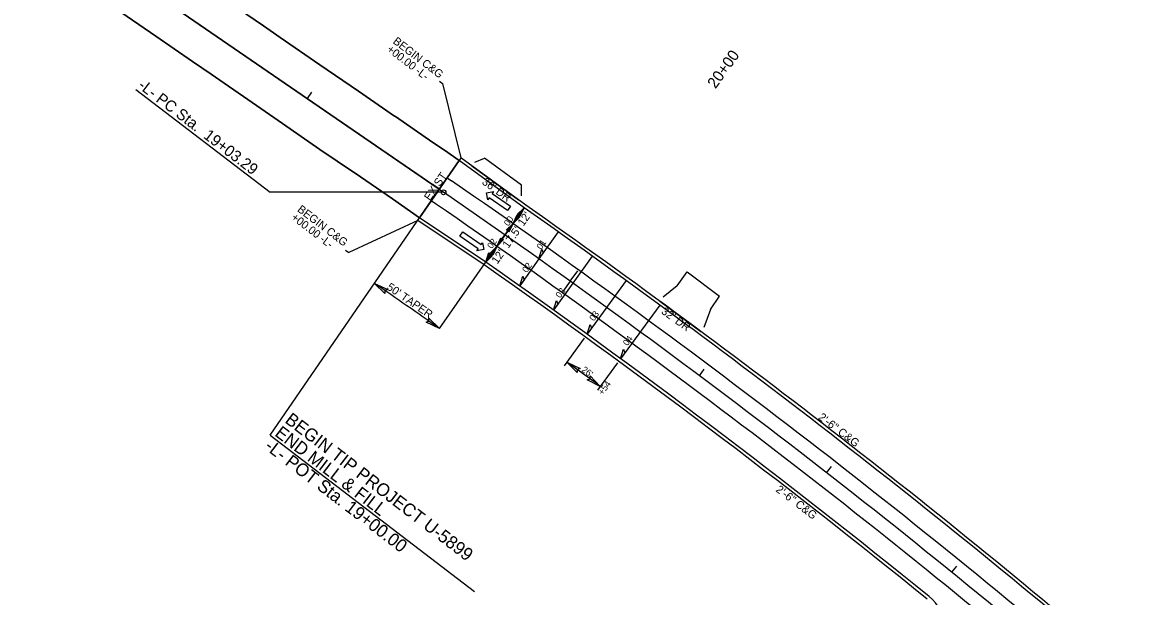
# Model space of a CAD drawing. Extents: x 1616561 to 1622460, y 896726 to 899651.
# Drawn here: x 1618541 to 1619243, y 898351 to 898710 of the extents above; entities that cross this region are included whole.
import ezdxf

# ---------------------------------------------------------------- set-up
doc = ezdxf.new("R2010")
doc.units = 0
for name, color, linetype in [('Old_Level_3', 7, 'Continuous'), ('Prop Conc Drive Radius Type', 7, 'Continuous'), ('Prop Dimension', 7, 'Continuous'), ('Prop DSN Text', 7, 'Continuous'), ('Prop Horizontal Alignment Tick Small', 7, 'Continuous'), ('Prop Lane Arrow CELL', 7, 'Continuous'), ('Prop North Arrow NAD83 for Plan Sheets CELL', 7, 'Continuous'), ('Prop Shade Light', 7, 'Continuous'), ('Prop Superelevation  Arrow CELL', 7, 'Continuous'), ('Prop Superelevation Label', 7, 'Continuous'), ('Prop Terminator CELL', 7, 'Continuous'), ('Scratch_Level_1', 7, 'Continuous'), ('Sheet Cutting Line CELL', 7, 'Continuous'), ('Sheet North Arrow CELL', 7, 'Continuous'), ('Sheet Sticker Preliminary CELL', 7, 'Continuous')]:
    doc.layers.add(name, color=color, linetype=linetype)

msp = doc.modelspace()

# ---------------------------------------------------------------- linework, layer by layer
at = {"layer": 'Old_Level_3'}
for p, q in [((1618796.38, 898598.52), (1618806.28, 898612.95)), ((1618806.28, 898612.95), (1618809, 898611.08)), ((1618799.08, 898596.66), (1618796.38, 898598.52))]:
    msp.add_line(p, q, dxfattribs=at)
for radius, start in [(5008.75, 49.34838), (4991.25, 49.50113)]:
    msp.add_arc((1615970.53, 894484.25), radius, start, 55.47944, dxfattribs=at)
at = {"layer": 'Prop Conc Drive Radius Type'}
for p, q in [((1618821.78, 898620.36), (1618850.89, 898599.2)), ((1618939.16, 898535.82), (1618964.88, 898516.84))]:
    msp.add_line(p, q, dxfattribs=at)
at = {"layer": 'Prop Dimension'}
for p, q in [((1618854.32, 898594.21), (1618847.43, 898584.38)), ((1618847.43, 898584.38), (1618837.37, 898570.06)), ((1618801.41, 898518.8), (1618842.4, 898577.22)), ((1618837.37, 898570.06), (1618830.48, 898560.23))]:
    msp.add_line(p, q, dxfattribs=at)
msp.add_arc((1615970.53, 894484.25), 4928.63, 54.94423, 55.51773, dxfattribs=at)
at = {"layer": 'Prop DSN Text'}
for p, q in [((1618801.42, 898673.34), (1618803.39, 898671.82)), ((1618803.39, 898671.82), (1618814.85, 898625.39)), ((1618787.93, 898586.26), (1618744.83, 898566.28)), ((1618742.85, 898567.79), (1618744.83, 898566.28))]:
    msp.add_line(p, q, dxfattribs=at)
at = {"layer": 'Prop Horizontal Alignment Tick Small'}
for p, q in [((1618814.85, 898625.39), (1618813.71, 898623.74)), ((1618855.5, 898595.82), (1618814.85, 898625.39)), ((1618787.93, 898586.26), (1618789.06, 898587.9)), ((1618829.37, 898558.57), (1618787.93, 898586.26))]:
    msp.add_line(p, q, dxfattribs=at)
for radius, start in [(5022.75, 49.34838), (4977.25, 50.95117)]:
    msp.add_arc((1615970.53, 894484.25), radius, start, 54.94423, dxfattribs=at)
at = {"layer": 'Prop Lane Arrow CELL'}
for p, q in [((1618830.84, 898603.55), (1618835.25, 898604.37)), ((1618831.65, 898599.2), (1618830.84, 898603.55)), ((1618832.51, 898600.43), (1618831.65, 898599.2)), ((1618843.99, 898592.43), (1618832.51, 898600.43)), ((1618835.25, 898604.37), (1618834.39, 898603.14)), ((1618834.39, 898603.14), (1618845.88, 898595.13)), ((1618845.88, 898595.13), (1618843.99, 898592.43)), ((1618814.13, 898576.45), (1618816.02, 898579.16)), ((1618825.61, 898568.45), (1618814.13, 898576.45)), ((1618816.02, 898579.16), (1618827.5, 898571.15)), ((1618827.5, 898571.15), (1618828.36, 898572.38)), ((1618828.36, 898572.38), (1618829.17, 898568.04)), ((1618824.76, 898567.22), (1618825.61, 898568.45)), ((1618829.17, 898568.04), (1618824.76, 898567.22))]:
    msp.add_line(p, q, dxfattribs=at)
at = {"layer": 'Prop North Arrow NAD83 for Plan Sheets CELL'}
for points in [[(1618830.48, 898560.23), (1618832.29, 898566.29), (1618833.14, 898564.02)], [(1618863.64, 898562.23), (1618865.49, 898568.28), (1618866.32, 898566)], [(1618851.64, 898545.31), (1618853.48, 898551.36), (1618854.31, 898549.08)], [(1618872.72, 898530.27), (1618874.59, 898536.31), (1618875.41, 898534.03)], [(1618893.72, 898515.12), (1618895.62, 898521.16), (1618896.43, 898518.87)], [(1618914.64, 898499.87), (1618916.57, 898505.89), (1618917.37, 898503.6)]]:
    msp.add_lwpolyline(points, close=True, dxfattribs=at)
at = {"layer": 'Prop Shade Light'}
for p, q in [((1618059.8, 899115.77), (1618801.33, 898605.73)), ((1618801.33, 898605.73), (1618059.8, 899115.77)), ((1618789.06, 898587.9), (1618801.33, 898605.73))]:
    msp.add_line(p, q, dxfattribs=at)
for points in [[(1618773.4, 898651.52), (1618750.87, 898667.1), (1618726.65, 898683.63), (1618702.01, 898700.61), (1618691.56, 898707.86), (1618670.18, 898722.47), (1618646.62, 898738.71), (1618621.31, 898755.98), (1618596.1, 898773.27), (1618578.76, 898785.19), (1618566.83, 898793.5), (1618556.18, 898800.72), (1618539.02, 898812.52)], [(1618532.75, 898764.19), (1618555.15, 898748.82), (1618573.55, 898736.29), (1618599.06, 898718.7), (1618624.26, 898701.44), (1618647.12, 898685.72), (1618658.86, 898677.65), (1618669.7, 898670.24), (1618679.04, 898663.8), (1618703.51, 898646.86), (1618726.83, 898630.68), (1618748.38, 898616.08), (1618748.82, 898615.73)], [(1618813.7, 898623.72), (1618804.53, 898630.14), (1618797.41, 898634.99), (1618773.92, 898651.22), (1618773.4, 898651.52)], [(1618801.33, 898605.73), (1618806.29, 898612.94), (1618813.7, 898623.72)], [(1618748.82, 898615.73), (1618772.07, 898599.73), (1618789.06, 898587.9)]]:
    msp.add_lwpolyline(points, dxfattribs=at)
at = {"layer": 'Prop Superelevation  Arrow CELL'}
for p, q in [((1618718.94, 898662.4), (1618721.77, 898666.52)), ((1618801.33, 898605.73), (1618804.16, 898609.85)), ((1618963.88, 898489.23), (1618966.87, 898493.24)), ((1619043.37, 898428.57), (1619046.45, 898432.52)), ((1619121.64, 898366.33), (1619124.79, 898370.21))]:
    msp.add_line(p, q, dxfattribs=at)
at = {"layer": 'Prop Superelevation Label'}
for q in [(1618887.85, 898554.8), (1618878.53, 898541.79)]:
    msp.add_line((1618883.19, 898548.3), q, dxfattribs=at)
at = {"layer": 'Prop Terminator CELL'}
for p, q in [((1618773.4, 898651.52), (1618773.92, 898651.22)), ((1618789.06, 898587.9), (1618813.71, 898623.74)), ((1618813.71, 898623.74), (1618789.06, 898587.9)), ((1618854.32, 898594.21), (1618813.71, 898623.74)), ((1618823.55, 898622.79), (1618829.68, 898625.17)), ((1618852.73, 898608.41), (1618829.68, 898625.17)), ((1618748.82, 898615.73), (1618748.38, 898616.08)), ((1618852.66, 898601.62), (1618852.73, 898608.41)), ((1618830.48, 898560.23), (1618789.06, 898587.9)), ((1618950.1, 898545.46), (1618956.21, 898554.21)), ((1618956.21, 898554.21), (1618976.37, 898538.91)), ((1618950.1, 898545.46), (1618941.17, 898538.38)), ((1618970.8, 898530.66), (1618976.37, 898538.91)), ((1618970.8, 898530.66), (1618966.66, 898519.26))]:
    msp.add_line(p, q, dxfattribs=at)
for points in [[(1618539.02, 898812.52), (1618556.18, 898800.72), (1618566.83, 898793.5), (1618578.76, 898785.19), (1618596.1, 898773.27), (1618621.31, 898755.98), (1618646.62, 898738.71), (1618670.18, 898722.47), (1618691.56, 898707.86), (1618702.01, 898700.61), (1618726.65, 898683.63), (1618750.87, 898667.1), (1618773.4, 898651.52)], [(1618748.38, 898616.08), (1618726.83, 898630.68), (1618703.51, 898646.86), (1618679.04, 898663.8), (1618669.7, 898670.24), (1618658.86, 898677.65), (1618647.12, 898685.72), (1618624.26, 898701.44), (1618599.06, 898718.7), (1618573.55, 898736.29), (1618555.15, 898748.82), (1618532.75, 898764.19)], [(1618773.92, 898651.22), (1618797.41, 898634.99), (1618804.53, 898630.14), (1618813.7, 898623.72)], [(1618789.06, 898587.9), (1618772.07, 898599.73), (1618748.82, 898615.73)]]:
    msp.add_lwpolyline(points, dxfattribs=at)
for points in [[(1618850.13, 898590), (1618854.32, 898594.21), (1618851.79, 898588.79), (1618851.37, 898590)], [(1618843.24, 898580.17), (1618847.43, 898584.38), (1618844.9, 898578.97), (1618844.48, 898580.18)], [(1618851.61, 898588.59), (1618847.43, 898584.38), (1618849.95, 898589.8), (1618850.38, 898588.59)], [(1618833.19, 898565.85), (1618837.37, 898570.06), (1618834.85, 898564.64), (1618834.43, 898565.85)], [(1618841.56, 898574.27), (1618837.37, 898570.06), (1618839.9, 898575.47), (1618840.32, 898574.26)], [(1618834.67, 898564.44), (1618830.48, 898560.23), (1618833.01, 898565.65), (1618833.43, 898564.44)], [(1618767.43, 898540.56), (1618760.88, 898546.93), (1618769.25, 898543.13), (1618767.4, 898542.46)], [(1618794.93, 898525.24), (1618801.41, 898518.8), (1618793.08, 898522.69), (1618794.94, 898523.34)], [(1618887.51, 898491.23), (1618881.13, 898497.77), (1618889.4, 898493.75), (1618887.53, 898493.13)], [(1618895.62, 898489.15), (1618901.96, 898482.58), (1618893.72, 898486.64), (1618895.59, 898487.25)]]:
    msp.add_lwpolyline(points, close=True, dxfattribs=at)
for centre, radius, start, end in [((1615970.53, 894484.25), 5020.75, 49.34838, 54.94423), ((1615970.53, 894484.25), 4979.25, 50.95117, 54.94423), ((1619090.36, 898330.22), 27, 315.29135, 50.95117)]:
    msp.add_arc(centre, radius, start, end, dxfattribs=at)
at = {"layer": 'Scratch_Level_1'}
msp.add_line((1618695.66, 898452.1), (1618823.31, 898354.34), dxfattribs=at)
at = {"layer": 'Sheet Cutting Line CELL'}
msp.add_line((1618059.8, 899115.77), (1618804.04, 898603.87), dxfattribs=at)
msp.add_arc((1615970.53, 894484.25), 5000, 49.34838, 55.47944, dxfattribs=at)
at = {"layer": 'Sheet North Arrow CELL'}
for p, q in [((1618611.83, 898668.16), (1618695.75, 898603.89)), ((1618695.66, 898452.1), (1618801.33, 898605.73)), ((1618804.04, 898603.87), (1618695.75, 898603.89))]:
    msp.add_line(p, q, dxfattribs=at)
msp.add_circle((1618804.04, 898603.87), 1.5, dxfattribs=at)
at = {"layer": 'Sheet Sticker Preliminary CELL'}
for p, q in [((1618830.48, 898560.23), (1618854.32, 898594.21)), ((1618875.65, 898579.15), (1618863.64, 898562.23)), ((1618896.91, 898563.99), (1618872.72, 898530.27)), ((1618863.64, 898562.23), (1618851.64, 898545.31)), ((1618918.08, 898548.72), (1618893.72, 898515.12)), ((1618939.18, 898533.34), (1618914.64, 898499.87)), ((1618891.96, 898512.7), (1618879.37, 898495.34)), ((1618912.8, 898497.36), (1618900.19, 898480.16))]:
    msp.add_line(p, q, dxfattribs=at)
msp.add_arc((1615970.53, 894484.25), 4957.81, 53.75247, 54.05041, dxfattribs=at)

# ---------------------------------------------------------------- texts
at = {"layer": 'Prop Dimension'}
for s, height, rotation, p in [('20+00', 7, 54.37127, (1618973.95, 898668.22)), ('EXIST', 5, 55.51165, (1618795.55, 898598.21)), ("36' DR", 5, 324.1734, (1618827.6, 898609.4)), ("12'", 5, 54.94423, (1618853.95, 898582.3)), ("17.5'", 5, 54.99363, (1618844.49, 898568.48)), ("12'", 5, 54.99363, (1618837.66, 898558.63)), ("50' TAPER", 5, 325.21632, (1618768.1, 898543.56)), ("32' DR", 5, 324.1734, (1618939.63, 898528.48)), ('2\'-6" C&G', 5.044, 322.55395, (1619037.76, 898462.42)), ('2\'-6" C&G', 5.044, 322.55395, (1619011.17, 898417.24))]:
    msp.add_text(s, height=height, rotation=rotation, dxfattribs=at).set_placement(p)
at = {"layer": 'Prop DSN Text'}
for s, p in [('BEGIN C&G', (1618772, 898697.42)), ('+00.00 -L-', (1618768.15, 898692.38)), ('BEGIN C&G', (1618712.28, 898592.35)), ('+00.00 -L-', (1618708.43, 898587.32))]:
    msp.add_text(s, height=5, rotation=322.55395, dxfattribs=at).set_placement(p)
at = {"layer": 'Scratch_Level_1'}
for s, p in [('BEGIN TIP PROJECT U-5899', (1618704.36, 898460.36)), ('END MILL & FILL', (1618698.04, 898452.1)), ('-L- POT Sta. 19+00.00 ', (1618691.72, 898443.85))]:
    msp.add_text(s, height=8, rotation=322.55395, dxfattribs=at).set_placement(p)
at = {"layer": 'Sheet North Arrow CELL'}
msp.add_text('-L- PC Sta.  19+03.29', height=7, rotation=322.55395, dxfattribs=at).set_placement((1618612.64, 898669.54))
at = {"layer": 'Sheet Sticker Preliminary CELL'}
for s, rotation, p in [('00', 54.94423, (1618844.64, 898582.37)), ('02', 54.94423, (1618834.19, 898568.3)), ('01', 54.64629, (1618865.07, 898567.69)), ('02', 54.64629, (1618856.07, 898553.27)), ('02', 54.34835, (1618876.9, 898537.46)), ('03', 54.05041, (1618897.98, 898523.05)), ('04', 53.75247, (1618918.96, 898507.59)), ("26'", 323.78685, (1618889.93, 898492.23)), ('+54', 53.78685, (1618903.5, 898476.79))]:
    msp.add_text(s, height=4, rotation=rotation, dxfattribs=at).set_placement(p)

doc.saveas('drawing.dxf')
